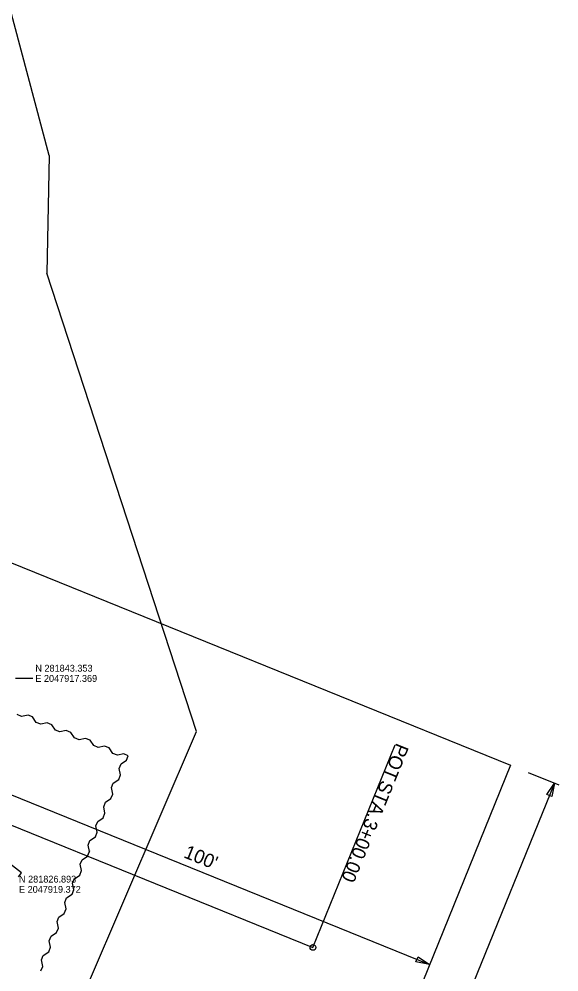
# Model space of a CAD drawing. Extents: x 2047712 to 2051245, y 280285 to 283042.
# Drawn here: x 2047930.5 to 2048041.5, y 281793.2 to 281989.1 of the extents above; entities that cross this region are included whole.
import ezdxf

# ---------------------------------------------------------------- set-up
doc = ezdxf.new("R2010")
doc.units = 0
for name, color, linetype in [('GE_P_Alignment', 7, 'Continuous'), ('RD_X_Concrete_Pad', 7, 'Continuous'), ('RD_X_GR_Rt', 7, 'Continuous'), ('SC_Scratch1', 7, 'Continuous'), ('SH_Data', 7, 'Continuous'), ('SV_Control_Point', 7, 'Continuous'), ('SV_X_Mon_Cells_Found', 7, 'Continuous'), ('TopoDOT_Transients', 7, 'Continuous')]:
    doc.layers.add(name, color=color, linetype=linetype)

msp = doc.modelspace()

# ---------------------------------------------------------------- linework, layer by layer
at = {"layer": 'GE_P_Alignment'}
msp.add_line((2047990.95, 281798.21), (2048007.88, 281839.9), dxfattribs=at)
msp.add_circle((2047990.95, 281798.21), 0.6, dxfattribs=at)
at = {"layer": 'RD_X_Concrete_Pad'}
msp.add_line((2047933.35, 281853.53), (2047929.82, 281853.53), dxfattribs=at)
at = {"layer": 'RD_X_GR_Rt'}
for p, q in [((2047887.35, 281894.22), (2048031.58, 281835.68)), ((2048031.58, 281835.68), (2047993.97, 281743.02)), ((2048035.19, 281834.21), (2048041.52, 281831.64)), ((2047922.28, 281832.28), (2048014.94, 281794.67)), ((2048040.59, 281832.02), (2048002.98, 281739.36))]:
    msp.add_line(p, q, dxfattribs=at)
for points in [[(2048040.06, 281829.22), (2048039.02, 281829.64), (2048040.59, 281832.02)], [(2048012.13, 281795.21), (2048012.55, 281796.24), (2048014.94, 281794.67)]]:
    msp.add_lwpolyline(points, close=True, dxfattribs=at)
at = {"layer": 'SC_Scratch1'}
msp.add_line((2047712.98, 281911.04), (2047990.95, 281798.21), dxfattribs=at)
at = {"layer": 'SH_Data'}
msp.add_line((2047931.01, 281813.54), (2047920.78, 281821.55), dxfattribs=at)
at = {"layer": 'SV_Control_Point'}
for p, q in [((2047936.73, 281961.09), (2047922.3, 282015.45)), ((2047936.73, 281961.09), (2047936.26, 281936.88)), ((2047966.98, 281842.6), (2047936.26, 281936.88)), ((2047944.6, 281790.37), (2047966.98, 281842.6))]:
    msp.add_line(p, q, dxfattribs=at)
at = {"layer": 'SV_X_Mon_Cells_Found'}
msp.add_line((2047930.4, 281812.75), (2047931.01, 281813.54), dxfattribs=at)
at = {"layer": 'TopoDOT_Transients'}
for p, q in [((2047931.05, 281845.73), (2047930.13, 281846.1)), ((2047932.38, 281846), (2047931.05, 281845.73)), ((2047933.3, 281845.62), (2047932.38, 281846)), ((2047934.06, 281844.5), (2047933.3, 281845.62)), ((2047934.99, 281844.13), (2047934.06, 281844.5)), ((2047936.31, 281844.4), (2047934.99, 281844.13)), ((2047937.24, 281844.02), (2047936.31, 281844.4)), ((2047938, 281842.9), (2047937.24, 281844.02)), ((2047938.93, 281842.53), (2047938, 281842.9)), ((2047940.25, 281842.8), (2047938.93, 281842.53)), ((2047941.18, 281842.42), (2047940.25, 281842.8)), ((2047941.94, 281841.31), (2047941.18, 281842.42)), ((2047942.87, 281840.93), (2047941.94, 281841.31)), ((2047944.19, 281841.2), (2047942.87, 281840.93)), ((2047945.12, 281840.83), (2047944.19, 281841.2)), ((2047945.88, 281839.71), (2047945.12, 281840.83)), ((2047946.8, 281839.33), (2047945.88, 281839.71)), ((2047948.13, 281839.6), (2047946.8, 281839.33)), ((2047949.06, 281839.23), (2047948.13, 281839.6)), ((2047949.82, 281838.11), (2047949.06, 281839.23)), ((2047950.74, 281837.73), (2047949.82, 281838.11)), ((2047952.07, 281838), (2047950.74, 281837.73)), ((2047951.5, 281835.94), (2047952.62, 281836.7)), ((2047952.99, 281837.63), (2047952.07, 281838)), ((2047952.62, 281836.7), (2047952.99, 281837.63)), ((2047951.12, 281835.01), (2047951.5, 281835.94)), ((2047951.39, 281833.69), (2047951.12, 281835.01)), ((2047949.9, 281832), (2047951.02, 281832.76)), ((2047951.02, 281832.76), (2047951.39, 281833.69)), ((2047949.52, 281831.08), (2047949.9, 281832)), ((2047949.8, 281829.75), (2047949.52, 281831.08)), ((2047948.3, 281828.07), (2047949.42, 281828.83)), ((2047949.42, 281828.83), (2047949.8, 281829.75)), ((2047947.93, 281827.14), (2047948.3, 281828.07)), ((2047948.2, 281825.81), (2047947.93, 281827.14)), ((2047946.7, 281824.13), (2047947.82, 281824.89)), ((2047947.82, 281824.89), (2047948.2, 281825.81)), ((2047946.33, 281823.2), (2047946.7, 281824.13)), ((2047946.6, 281821.88), (2047946.33, 281823.2)), ((2047945.11, 281820.19), (2047946.22, 281820.95)), ((2047946.22, 281820.95), (2047946.6, 281821.88)), ((2047944.73, 281819.26), (2047945.11, 281820.19)), ((2047945, 281817.94), (2047944.73, 281819.26)), ((2047944.62, 281817.01), (2047945.08, 281818.12)), ((2047944.62, 281817.01), (2047945, 281817.94)), ((2047943.13, 281815.33), (2047943.51, 281816.25)), ((2047943.4, 281814), (2047943.13, 281815.33)), ((2047943.51, 281816.25), (2047944.62, 281817.01)), ((2047943.03, 281813.07), (2047943.4, 281814)), ((2047941.53, 281811.39), (2047941.91, 281812.31)), ((2047941.8, 281810.06), (2047941.53, 281811.39)), ((2047941.91, 281812.31), (2047943.03, 281813.07)), ((2047941.43, 281809.14), (2047941.8, 281810.06)), ((2047939.93, 281807.45), (2047940.31, 281808.38)), ((2047940.21, 281806.12), (2047939.93, 281807.45)), ((2047940.31, 281808.38), (2047941.43, 281809.14)), ((2047939.83, 281805.2), (2047940.21, 281806.12)), ((2047938.34, 281803.51), (2047938.71, 281804.44)), ((2047938.61, 281802.19), (2047938.34, 281803.51)), ((2047938.71, 281804.44), (2047939.83, 281805.2)), ((2047938.23, 281801.26), (2047938.61, 281802.19)), ((2047936.74, 281799.57), (2047937.11, 281800.5)), ((2047937.01, 281798.25), (2047936.74, 281799.57)), ((2047937.11, 281800.5), (2047938.23, 281801.26)), ((2047936.63, 281797.32), (2047937.01, 281798.25)), ((2047935.14, 281795.64), (2047935.51, 281796.56)), ((2047935.41, 281794.31), (2047935.14, 281795.64)), ((2047935.51, 281796.56), (2047936.63, 281797.32)), ((2047935.03, 281793.38), (2047935.41, 281794.31))]:
    msp.add_line(p, q, dxfattribs=at)

# ---------------------------------------------------------------- texts
at = {"layer": 'GE_P_Alignment'}
for s, p in [('POT', (2048008.13, 281840.41)), (' STA. ', (2048005.42, 281833.74)), ('3+00.00', (2048001.87, 281824.98))]:
    msp.add_text(s, height=2.8, rotation=247.9067, dxfattribs=at).set_placement(p)
at = {"layer": 'RD_X_Concrete_Pad'}
for s, p in [('N 281843.353', (2047933.88, 281854.93)), ('E 2047917.369', (2047933.88, 281852.83)), ('N 281826.893', (2047930.52, 281811.55)), ('E 2047919.372', (2047930.52, 281809.45))]:
    msp.add_text(s, height=1.4, dxfattribs=at).set_placement(p)
at = {"layer": 'RD_X_GR_Rt'}
msp.add_text("100'", height=2.8, rotation=337.9067, dxfattribs=at).set_placement((2047964.2, 281816.77))

doc.saveas('drawing.dxf')
